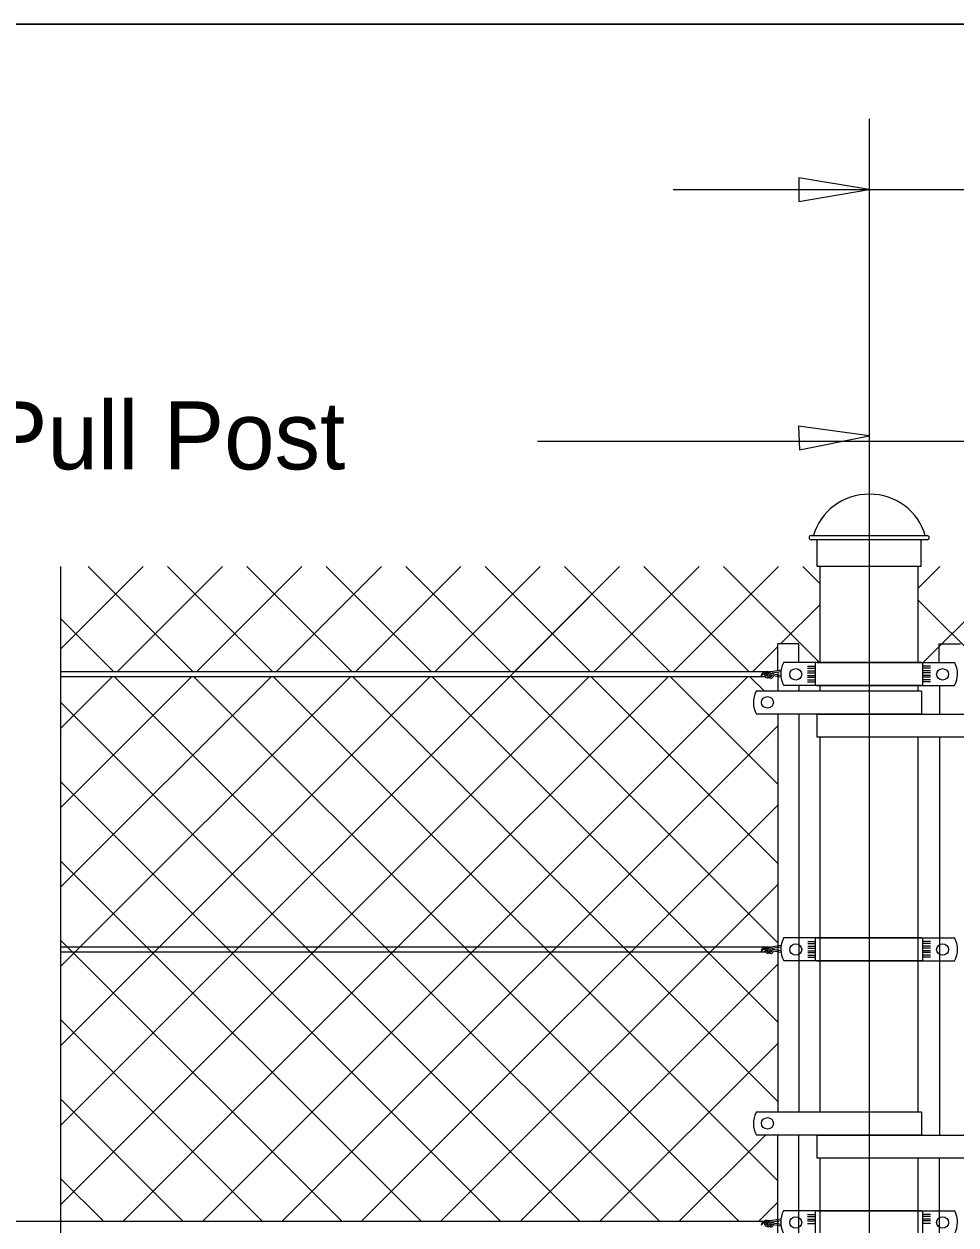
# Model space of a CAD drawing. Extents: x 0 to 41.2, y 0 to 26.
# Drawn here: x 23.735 to 26.501, y 22.394 to 25.96 of the extents above; entities that cross this region are included whole.
import ezdxf

# ---------------------------------------------------------------- set-up
doc = ezdxf.new("R2010")
doc.units = 0
for name, color, linetype in [('ActivePts-ConstElements', 7, 'Continuous'), ('CL_Major', 7, 'Continuous'), ('Dimension', 7, 'Continuous'), ('Miscellaneous', 7, 'Continuous'), ('Miscellaneous1', 7, 'Continuous'), ('SteelMisc', 7, 'Continuous'), ('TextStructures', 7, 'Continuous')]:
    doc.layers.add(name, color=color, linetype=linetype)

msp = doc.modelspace()

# ---------------------------------------------------------------- linework, layer by layer
at = {"layer": 'ActivePts-ConstElements'}
msp.add_lwpolyline([(0, 0), (41.2106, 0), (41.2106, 25.96), (0, 25.96)], close=True, dxfattribs=at)
at = {"layer": 'CL_Major'}
msp.add_line((26.2429, 25.6784), (26.2429, 12.3953), dxfattribs=at)
at = {"layer": 'Dimension'}
msp.add_line((25.6609, 25.4682), (35.6727, 25.4682), dxfattribs=at)
for points in [[(26.2429, 25.4682), (26.0347, 25.5034), (26.0347, 25.4329)], [(26.2429, 24.737), (26.0337, 24.766), (26.0358, 24.6954)]]:
    msp.add_lwpolyline(points, close=True, dxfattribs=at)
msp.add_lwpolyline([(23.8431, 24.349), (23.8431, 21.1819), (23.9465, 21.1819), (23.8431, 21.1369), (23.7398, 21.0919), (23.8431, 21.0919), (23.8431, 20.1983)], dxfattribs=at)
msp.add_open_spline([(25.2588, 24.7214), (25.7125, 24.7214), (27.3088, 24.7214), (28.5763, 24.9737)], degree=2, dxfattribs=at)
at = {"layer": 'Miscellaneous'}
for p, q in [((24.0882, 24.349), (23.8431, 24.104)), ((24.2372, 24.0365), (23.9247, 24.349)), ((24.3239, 24.349), (24.0113, 24.0365)), ((24.4729, 24.0365), (24.1604, 24.349)), ((24.5596, 24.349), (24.247, 24.0365)), ((24.7086, 24.0365), (24.3961, 24.349)), ((24.7953, 24.349), (24.4827, 24.0365)), ((24.9443, 24.0365), (24.6318, 24.349)), ((25.031, 24.349), (24.7184, 24.0365)), ((25.18, 24.0365), (24.8675, 24.349)), ((25.2667, 24.349), (24.9541, 24.0365)), ((25.4157, 24.0365), (25.1032, 24.349)), ((25.5024, 24.349), (25.1898, 24.0365)), ((25.6514, 24.0365), (25.3389, 24.349)), ((25.7381, 24.349), (25.4255, 24.0365)), ((25.8871, 24.0365), (25.5746, 24.349)), ((25.9738, 24.349), (25.6612, 24.0365)), ((26.0957, 24.0637), (25.8103, 24.349)), ((26.0971, 24.298), (26.046, 24.349)), ((26.3887, 24.2852), (26.4526, 24.349)), ((26.4023, 24.0631), (26.6883, 24.349)), ((25.4108, 24.2575), (23.8431, 22.6898)), ((26.3887, 24.2494), (26.6017, 24.0365)), ((26.0971, 24.2366), (25.9803, 24.1198)), ((24.0015, 24.0365), (23.8431, 24.1949)), ((25.972, 24.1116), (25.8969, 24.0365)), ((25.4108, 24.0218), (23.8431, 22.4541)), ((24.9394, 24.0218), (23.8431, 22.9255)), ((24.7037, 24.0218), (23.8431, 23.1612)), ((24.468, 24.0218), (23.8431, 23.3969)), ((24.2323, 24.0218), (23.8431, 23.6326)), ((23.9966, 24.0218), (23.8431, 23.8683)), ((25.6205, 22.4048), (24.0035, 24.0218)), ((25.6465, 24.0218), (24.0295, 22.4048)), ((25.8562, 22.4048), (24.2392, 24.0218)), ((25.8822, 24.0218), (24.2652, 22.4048)), ((25.972, 22.5246), (24.4749, 24.0218)), ((25.972, 22.7603), (24.7106, 24.0218)), ((25.972, 22.996), (24.9463, 24.0218)), ((25.972, 23.2317), (25.182, 24.0218)), ((25.972, 23.4674), (25.4177, 24.0218)), ((25.972, 23.7031), (25.6534, 24.0218)), ((25.9323, 23.9786), (25.8891, 24.0218)), ((25.3848, 22.4048), (23.8431, 23.9464)), ((25.972, 23.8759), (24.5009, 22.4048)), ((25.1491, 22.4048), (23.8431, 23.7107)), ((25.972, 23.6402), (24.7366, 22.4048)), ((24.9134, 22.4048), (23.8431, 23.475)), ((25.972, 23.4045), (24.9723, 22.4048)), ((24.6777, 22.4048), (23.8431, 23.2393)), ((25.972, 23.1688), (25.208, 22.4048)), ((24.442, 22.4048), (23.8431, 23.0036)), ((25.972, 22.9331), (25.4437, 22.4048)), ((24.2063, 22.4048), (23.8447, 22.7664)), ((25.9356, 22.6609), (25.6794, 22.4048)), ((23.9706, 22.4048), (23.8431, 22.5322)), ((25.972, 22.4617), (25.9151, 22.4048))]:
    msp.add_line(p, q, dxfattribs=at)
at = {"layer": 'Miscellaneous1'}
msp.add_lwpolyline([(0, 25.96), (41.2106, 25.96), (41.2106, 0), (0, 0)], close=True, dxfattribs=at)
at = {"layer": 'SteelMisc'}
for p, q in [((26.0706, 24.441), (26.4152, 24.441)), ((26.4152, 24.4288), (26.0706, 24.4288)), ((26.0889, 24.349), (26.0889, 24.4288)), ((26.397, 24.349), (26.397, 24.4288)), ((26.397, 24.349), (26.0889, 24.349)), ((26.0971, 24.0636), (26.0971, 24.349)), ((26.3887, 24.0636), (26.3887, 24.349)), ((25.972, 24.0396), (25.972, 24.1198)), ((26.0345, 24.1198), (25.972, 24.1198)), ((26.0345, 24.0636), (26.0345, 24.1198)), ((26.4512, 24.0636), (26.4512, 24.1198)), ((26.4512, 24.1198), (26.5137, 24.1198)), ((25.9336, 24.0365), (23.8431, 24.0365)), ((25.9817, 24.0412), (25.9524, 24.0366)), ((25.9809, 24.0362), (25.9549, 24.0321)), ((25.972, 24.0366), (25.972, 23.9786)), ((26.3988, 24.0637), (25.989, 24.0637)), ((26.0604, 24.0528), (26.0833, 24.0528)), ((26.0604, 24.0473), (26.0833, 24.0473)), ((26.0604, 24.0393), (26.0833, 24.0393)), ((26.0833, 23.9959), (26.0833, 24.0637)), ((26.0872, 24.0637), (26.4969, 24.0637)), ((26.4254, 24.0528), (26.4024, 24.0528)), ((26.4254, 24.0473), (26.4024, 24.0473)), ((26.4254, 24.0393), (26.4024, 24.0393)), ((26.4025, 23.9959), (26.4025, 24.0637)), ((25.9349, 24.0218), (23.8431, 24.0218)), ((25.981, 24.0207), (25.9474, 24.0264)), ((25.9806, 24.0255), (25.9508, 24.0304)), ((25.972, 24.0347), (25.972, 24.0269)), ((26.0604, 24.0337), (26.0833, 24.0337)), ((26.0604, 24.0257), (26.0833, 24.0257)), ((26.0604, 24.0202), (26.0833, 24.0202)), ((26.0604, 24.0122), (26.0833, 24.0122)), ((26.0604, 24.0066), (26.0833, 24.0066)), ((26.4254, 24.0337), (26.4024, 24.0337)), ((26.4254, 24.0257), (26.4024, 24.0257)), ((26.4254, 24.0202), (26.4024, 24.0202)), ((26.4254, 24.0122), (26.4024, 24.0122)), ((26.4254, 24.0066), (26.4024, 24.0066)), ((26.3988, 23.9786), (25.9077, 23.9786)), ((26.3988, 23.9959), (25.9894, 23.9959)), ((26.0345, 23.9959), (26.0345, 23.9786)), ((26.0872, 23.9959), (26.4966, 23.9959)), ((26.0971, 23.9786), (26.0971, 23.9959)), ((26.3888, 23.9786), (26.3888, 23.9959)), ((26.3988, 23.9786), (26.3988, 23.9109)), ((26.4513, 23.9959), (26.4513, 23.9109)), ((26.3988, 23.9109), (25.9084, 23.9109)), ((25.972, 23.9109), (25.972, 22.7286)), ((26.0345, 23.9109), (26.0345, 22.7286)), ((26.0872, 23.9109), (26.0872, 23.8433)), ((26.0872, 23.9109), (26.5783, 23.9109)), ((26.0872, 23.8433), (26.5776, 23.8433)), ((26.0971, 22.7286), (26.0971, 23.8433)), ((26.3888, 22.7286), (26.3888, 23.8433)), ((26.4513, 23.8433), (26.4513, 22.6609)), ((25.9338, 23.219), (23.8433, 23.219)), ((25.9818, 23.2237), (25.9526, 23.2191)), ((25.9811, 23.2187), (25.9551, 23.2146)), ((25.9722, 23.2172), (25.9722, 23.2094)), ((26.3989, 23.2462), (25.9891, 23.2462)), ((26.0605, 23.2354), (26.0835, 23.2354)), ((26.0605, 23.2298), (26.0835, 23.2298)), ((26.0605, 23.2218), (26.0835, 23.2218)), ((26.0605, 23.2163), (26.0835, 23.2163)), ((26.0835, 23.1785), (26.0835, 23.2462)), ((26.0874, 23.2462), (26.4971, 23.2462)), ((26.4255, 23.2354), (26.4026, 23.2354)), ((26.4255, 23.2298), (26.4026, 23.2298)), ((26.4255, 23.2218), (26.4026, 23.2218)), ((26.4255, 23.2163), (26.4026, 23.2163)), ((26.4027, 23.1785), (26.4027, 23.2462)), ((25.9351, 23.2043), (23.8433, 23.2043)), ((25.9812, 23.2033), (25.9476, 23.2089)), ((25.9808, 23.2081), (25.951, 23.213)), ((26.0605, 23.2083), (26.0835, 23.2083)), ((26.0605, 23.2027), (26.0835, 23.2027)), ((26.0605, 23.1947), (26.0835, 23.1947)), ((26.0605, 23.1892), (26.0835, 23.1892)), ((26.4255, 23.2083), (26.4026, 23.2083)), ((26.4255, 23.2027), (26.4026, 23.2027)), ((26.4255, 23.1947), (26.4026, 23.1947)), ((26.4255, 23.1892), (26.4026, 23.1892)), ((26.3989, 23.1785), (25.9896, 23.1785)), ((26.0874, 23.1785), (26.4967, 23.1785)), ((26.4513, 22.9288), (26.4513, 22.7653)), ((26.3988, 22.7286), (25.9077, 22.7286)), ((26.3988, 22.7286), (26.3988, 22.6609)), ((26.3988, 22.6609), (25.9084, 22.6609)), ((25.972, 21.4785), (25.972, 22.6609)), ((26.0345, 21.4785), (26.0345, 22.6609)), ((26.0872, 22.6609), (26.0872, 22.5933)), ((26.0872, 22.6609), (26.5783, 22.6609)), ((26.0872, 22.5933), (26.5776, 22.5933)), ((26.0971, 21.4785), (26.0971, 22.5933)), ((26.3888, 21.4785), (26.3888, 22.5933)), ((26.4513, 21.4109), (26.4513, 22.5933)), ((26.3988, 22.4358), (25.989, 22.4358)), ((26.0833, 22.3681), (26.0833, 22.4358)), ((26.0872, 22.4358), (26.4969, 22.4358)), ((26.4025, 22.3681), (26.4025, 22.4358)), ((22.5265, 22.4048), (25.929, 22.4048)), ((25.9815, 22.3908), (25.9472, 22.3965)), ((25.9809, 22.3956), (25.9504, 22.4006)), ((25.9811, 22.4112), (25.9549, 22.4069)), ((25.9807, 22.4063), (25.955, 22.402)), ((25.972, 22.4048), (25.972, 22.397)), ((26.0604, 22.425), (26.0833, 22.425)), ((26.0604, 22.4195), (26.0833, 22.4195)), ((26.0604, 22.4114), (26.0833, 22.4114)), ((26.0604, 22.4059), (26.0833, 22.4059)), ((26.0604, 22.3979), (26.0833, 22.3979)), ((26.4254, 22.425), (26.4024, 22.425)), ((26.4254, 22.4195), (26.4024, 22.4195)), ((26.4254, 22.4114), (26.4024, 22.4114)), ((26.4254, 22.4059), (26.4024, 22.4059)), ((26.4254, 22.3979), (26.4024, 22.3979))]:
    msp.add_line(p, q, dxfattribs=at)
for centre, start, end in [((26.0707, 24.4347), 91.1647, 268.8353), ((26.415, 24.4347), 271.1647, 88.8353)]:
    msp.add_arc(centre, 0.00613, start, end, dxfattribs=at)
for centre, major_axis, ratio, start_param, end_param in [((26.2436, 24.4), (0.1711, 0), 0.957868, 0.252602, 2.888574), ((25.9368, 24.0233), (0.0142, 0), 0.957868, 1.486836, 3.141593), ((25.9415, 24.0288), (0.00872, 0), 0.957868, 1.29026, 2.959852), ((25.948, 24.0283), (0.00872, 0), 0.957868, 1.29026, 4.182385), ((25.9537, 24.0274), (-0.0115, -0.0041), 0.737732, 4.35367, 7.47816), ((26.0582, 24.03), (-0.0776, 0), 0.957868, 5.81433, 6.762456), ((26.4276, 24.03), (0.0776, 0), 0.957868, 5.803915, 6.752041), ((25.9448, 24.0082), (-0.0274, 0), 0.957868, 5.133531, 5.654664), ((25.9419, 24.0278), (-0.00944, 0), 0.957868, 6.009018, 8.249874), ((25.9415, 24.0288), (0.00503, 0), 0.92697, 1.570796, 4.502291), ((25.9525, 24.0259), (-0.00527, 0), 0.957868, 5.22362, 7.507542), ((25.9503, 24.025), (-0.00301, 0), 0.957868, 6.141288, 6.278592), ((25.9556, 24.0225), (-0.00982, 0), 0.957868, 4.777514, 5.62749), ((25.9503, 24.025), (-0.00301, 0), 0.957868, 1.11255, 2.999696), ((25.9497, 24.0272), (0.00453, 0), 0.957868, 0.731188, 1.133458), ((25.9498, 24.0267), (0.0095, 0), 0.957868, 5.011765, 6.030719), ((25.9498, 24.0267), (0.0095, 0), 0.957868, 0.230606, 0.609214), ((25.9771, 23.9454), (-0.0776, 0), 0.957868, 5.821213, 6.765127), ((25.9369, 23.2058), (0.0142, 0), 0.957868, 1.486836, 3.141593), ((25.9417, 23.2113), (0.00872, 0), 0.957868, 1.29026, 2.959852), ((25.9417, 23.2113), (0.00503, 0), 0.92697, 1.570796, 4.502291), ((25.9482, 23.2108), (0.00872, 0), 0.957868, 1.29026, 4.182385), ((25.9539, 23.2099), (-0.0115, -0.0041), 0.737732, 4.35367, 7.47816), ((26.0584, 23.2125), (-0.0776, 0), 0.957868, 5.81433, 6.762456), ((26.4277, 23.2125), (0.0776, 0), 0.957868, 5.803915, 6.752041), ((25.9449, 23.1908), (-0.0274, 0), 0.957868, 5.133531, 5.654664), ((25.9421, 23.2104), (-0.00944, 0), 0.957868, 6.009018, 8.249874), ((25.9526, 23.2084), (-0.00527, 0), 0.957868, 5.22362, 7.507542), ((25.9505, 23.2075), (-0.00301, 0), 0.957868, 6.141288, 6.278592), ((25.9558, 23.205), (-0.00982, 0), 0.957868, 4.777514, 5.62749), ((25.9505, 23.2075), (-0.00301, 0), 0.957868, 1.11255, 2.999696), ((25.9498, 23.2097), (0.00453, 0), 0.957868, 0.731188, 1.133458), ((25.9499, 23.2092), (0.0095, 0), 0.957868, 5.011765, 6.030719), ((25.9499, 23.2092), (0.0095, 0), 0.957868, 0.230606, 0.609214), ((25.9771, 22.6954), (-0.0776, 0), 0.957868, 5.821213, 6.765127), ((26.0582, 22.4022), (-0.0776, 0), 0.957868, 5.81433, 6.762456), ((26.4276, 22.4022), (0.0776, 0), 0.957868, 5.803915, 6.752041), ((25.9368, 22.3934), (0.0142, 0), 0.957868, 1.427866, 3.10804), ((25.9448, 22.3784), (-0.0274, 0), 0.957868, 5.133531, 5.652105), ((25.9419, 22.398), (-0.00944, 0), 0.957868, 5.913863, 8.249874), ((25.9415, 22.3989), (0.00872, 0), 0.957868, 1.103089, 2.861068), ((25.9415, 22.3989), (0.00503, 0), 0.92697, 1.632124, 4.493683), ((25.948, 22.3984), (0.00872, 0), 0.957868, 1.202886, 4.168248), ((25.9537, 22.3976), (-0.0115, -0.0041), 0.737732, 4.35367, 7.518104), ((25.9525, 22.396), (-0.00527, 0), 0.957868, 5.822913, 6.90541), ((25.9503, 22.3951), (-0.00301, 0), 0.957868, 5.79353, 6.278592), ((25.9556, 22.3927), (-0.00982, 0), 0.957868, 4.777514, 5.64637), ((25.9503, 22.3951), (-0.00301, 0), 0.957868, 0.785393, 3.285656), ((25.9497, 22.3973), (0.00453, 0), 0.957868, 0.731188, 1.133458), ((25.9498, 22.3968), (0.0095, 0), 0.957868, 0.267283, 0.660004), ((25.9498, 22.3968), (0.0095, 0), 0.957868, 5.036011, 6.030719)]:
    msp.add_ellipse(centre, major_axis=major_axis, ratio=ratio, start_param=start_param, end_param=end_param, dxfattribs=at)
for centre, major_axis in [((26.0249, 24.0291), (0.0178, 0)), ((26.4609, 24.0291), (-0.0178, 0)), ((25.9412, 23.9458), (0.0177, 0)), ((26.025, 23.2117), (0.0178, 0)), ((26.4611, 23.2117), (-0.0178, 0)), ((25.9412, 22.6958), (0.0177, 0)), ((26.0249, 22.4013), (0.0178, 0)), ((26.4609, 22.4013), (-0.0178, 0))]:
    msp.add_ellipse(centre, major_axis=major_axis, ratio=0.957868, dxfattribs=at)

# ---------------------------------------------------------------- texts
at = {"layer": 'TextStructures'}
msp.add_text('℄ Pull Post', height=0.2016, dxfattribs=at).set_placement((23.4401, 24.6377))

doc.saveas('drawing.dxf')
